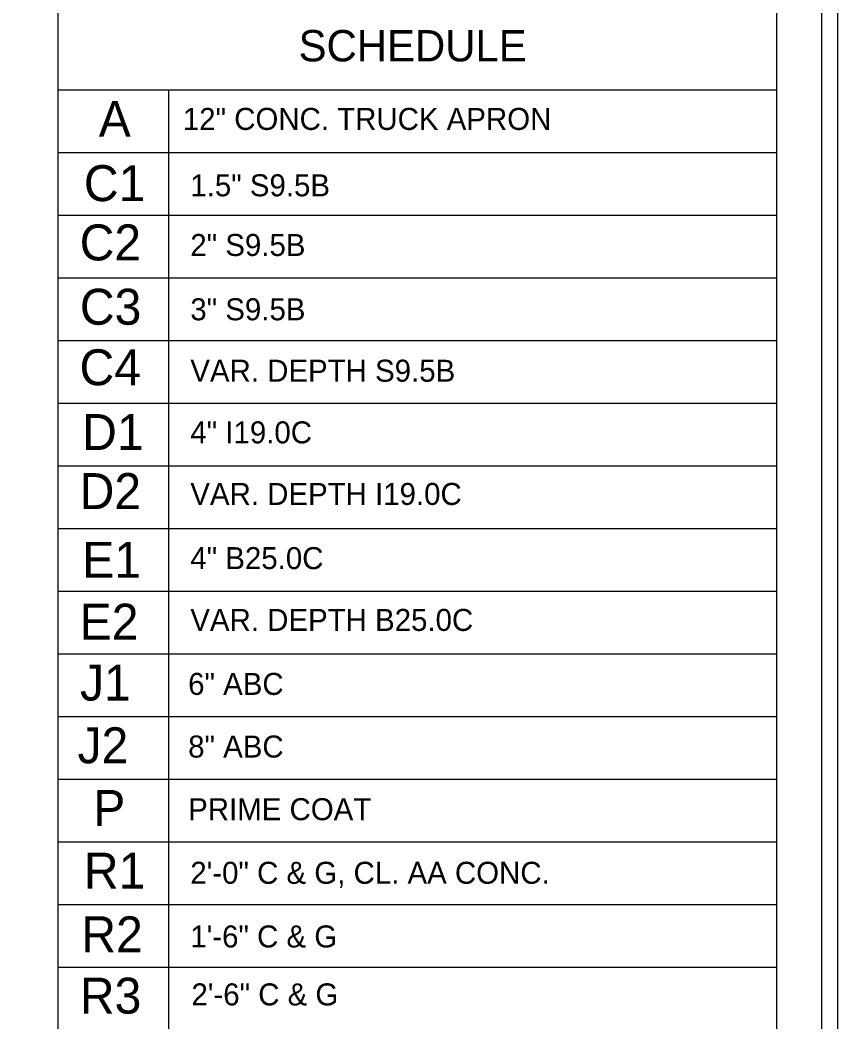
# Model space of a CAD drawing. Extents: x 958711 to 962106, y 831169 to 840840.
# Drawn here: x 960167.1 to 960394.8, y 839066.9 to 839345.8 of the extents above; entities that cross this region are included whole.
import ezdxf

# ---------------------------------------------------------------- set-up
doc = ezdxf.new("R2010")
doc.units = 0
for name, color, linetype in [('Old_Level_50', 7, 'Continuous'), ('Prop Pavement Schedule Description CELL', 7, 'Continuous'), ('Sheet Plot Border Inside CELL', 7, 'Continuous'), ('Sheet Plot Border Outside CELL', 7, 'Continuous'), ('Sheet Typical CELL', 7, 'Continuous')]:
    doc.layers.add(name, color=color, linetype=linetype)

msp = doc.modelspace()

# ---------------------------------------------------------------- linework, layer by layer
at = {"layer": 'Old_Level_50'}
for p, q in [((960177.74, 838890.34), (960177.74, 839362.65)), ((960177.74, 839326.37), (960377.78, 839326.37)), ((960177.74, 839326.37), (960377.78, 839326.37)), ((960208.47, 839326.37), (960208.47, 838890.34)), ((960177.74, 839308.93), (960377.78, 839308.93)), ((960177.74, 839291.49), (960377.78, 839291.49)), ((960177.74, 839291.49), (960377.78, 839291.49)), ((960177.74, 839291.49), (960377.78, 839291.49)), ((960177.74, 839274.04), (960377.78, 839274.04)), ((960177.74, 839274.04), (960377.78, 839274.04)), ((960177.74, 839274.04), (960377.78, 839274.04)), ((960177.74, 839256.6), (960377.78, 839256.6)), ((960177.74, 839239.16), (960377.78, 839239.16)), ((960177.74, 839221.72), (960377.78, 839221.72)), ((960177.74, 839204.28), (960377.78, 839204.28)), ((960177.74, 839186.84), (960377.78, 839186.84)), ((960177.74, 839169.4), (960377.78, 839169.4)), ((960177.74, 839151.96), (960377.78, 839151.96)), ((960177.74, 839134.51), (960377.78, 839134.51)), ((960177.74, 839117.07), (960377.78, 839117.07)), ((960177.74, 839099.63), (960377.78, 839099.63)), ((960177.74, 839082.19), (960377.78, 839082.19))]:
    msp.add_line(p, q, dxfattribs=at)
at = {"layer": 'Sheet Plot Border Inside CELL'}
msp.add_lwpolyline([(960390.3, 839592.94), (958723.8, 839592.94), (958723.8, 838537.84), (960390.3, 838537.84)], close=True, dxfattribs=at)
at = {"layer": 'Sheet Plot Border Outside CELL'}
msp.add_lwpolyline([(960394.8, 839615.39), (958710.8, 839615.39), (958710.8, 838515.39), (960394.8, 838515.39)], close=True, dxfattribs=at)
at = {"layer": 'Sheet Typical CELL'}
msp.add_lwpolyline([(960377.8, 839590.39), (958877.8, 839590.39), (958877.8, 838540.39), (960377.8, 838540.39)], close=True, dxfattribs=at)

# ---------------------------------------------------------------- texts
at = {"layer": 'Old_Level_50'}
msp.add_text('SCHEDULE', height=8.721, dxfattribs=at).set_placement((960244.65, 839334.32))
at = {"layer": 'Prop Pavement Schedule Description CELL'}
for s, height, p in [('A', 10, (960189.02, 839313.32)), ('12" CONC. TRUCK APRON', 6.1255, (960212.43, 839315.24)), ('C1', 10.005, (960184.88, 839295.42)), ('1.5" S9.5B', 6.126, (960214.51, 839296.76)), ('C2', 10.005, (960183.71, 839278.92)), ('2" S9.5B', 6.126, (960214.51, 839280.15)), ('C3', 10.005, (960183.77, 839261.02)), ('3" S9.5B', 6.126, (960214.51, 839262.25)), ('C4', 10.005, (960183.67, 839244.16)), ('VAR. DEPTH S9.5B', 6.1255, (960214.51, 839245.15)), ('D1', 10.005, (960184.41, 839226.14)), ('4" I19.0C', 6.126, (960214.51, 839227.99)), ('D2', 10.005, (960183.71, 839209.7)), ('VAR. DEPTH I19.0C', 6.1255, (960214.51, 839210.85)), ('E1', 10.005, (960184.41, 839190.57)), ('4" B25.0C', 6.126, (960214.51, 839192.98)), ('E2', 10.005, (960183.71, 839173.36)), ('VAR. DEPTH B25.0C', 6.1255, (960214.51, 839175.78)), ('J1', 10.005, (960183.81, 839156.39)), ('6" ABC', 6.126, (960213.91, 839157.97)), ('J2', 10.005, (960183.11, 839138.94)), ('8" ABC', 6.126, (960213.91, 839140.53)), ('P', 10, (960187.49, 839121.5)), ('PRIME COAT', 6.126, (960213.91, 839123.09)), ('R1', 10.005, (960184.88, 839104.06)), ('2\'-0" C & G, CL. AA CONC.', 6.1255, (960214.51, 839105.39)), ('R2', 10.005, (960184.18, 839086.33)), ('1\'-6" C & G', 6.1255, (960214.51, 839087.67)), ('R3', 10.005, (960183.77, 839069.25)), ('2\'-6" C & G', 6.1255, (960214.83, 839071.54))]:
    msp.add_text(s, height=height, dxfattribs=at).set_placement(p)

doc.saveas('drawing.dxf')
